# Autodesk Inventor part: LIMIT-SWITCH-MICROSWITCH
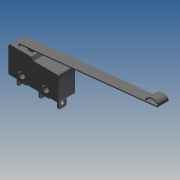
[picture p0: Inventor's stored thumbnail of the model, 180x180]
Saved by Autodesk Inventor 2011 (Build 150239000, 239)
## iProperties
Created: 2010-08
Part Number: LIMIT-SWITCH-MICROSWITCH
Document SubType Name: Modeling
Density: 1 g/cm^3
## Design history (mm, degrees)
feature "Base1"
workplane "Work Plane1"
body "Solid1"
